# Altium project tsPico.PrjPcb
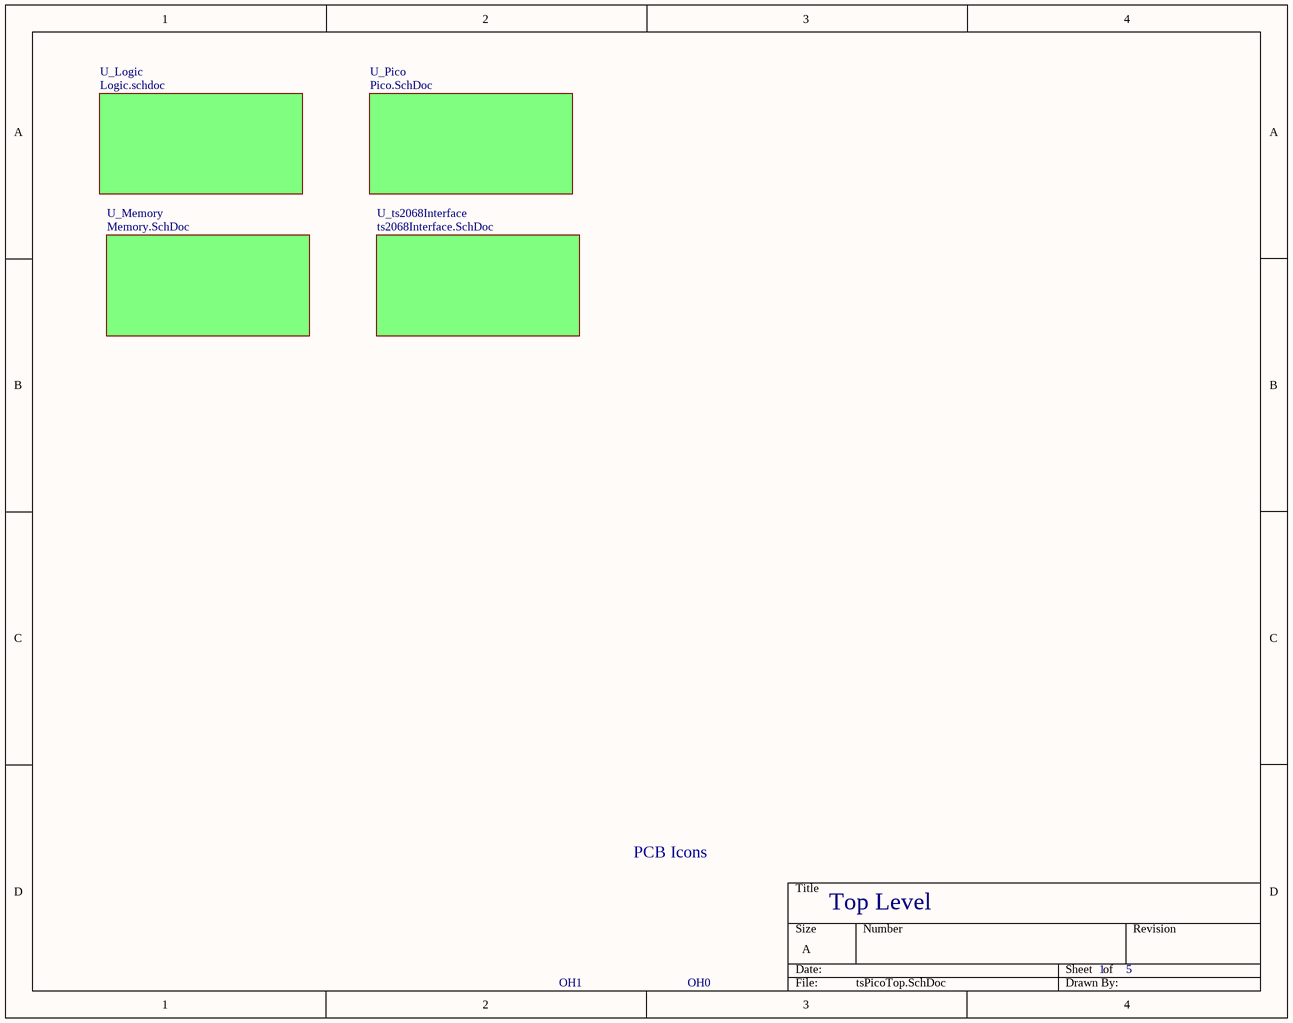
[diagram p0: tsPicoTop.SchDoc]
5 sheets, 52 parts. Net scope: global (net labels, ports and power ports of the same name join across sheets).
Sheets:
  tsPicoTop.SchDoc
    U_Logic = Logic.schdoc
    U_Memory = Memory.SchDoc
    U_Pico = Pico.SchDoc
    U_ts2068Interface = ts2068Interface.SchDoc

## Sheet tsPicoTop.SchDoc
size A; SheetNumber: 1; SheetTotal: 5

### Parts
OH0  OPENHW_PCB  [OpenHW]  (value not drawn)
OH1  OPENHW_SCH  (value not drawn)

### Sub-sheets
U_Logic = Logic.schdoc: no entries
U_Memory = Memory.SchDoc: no entries
U_Pico = Pico.SchDoc: no entries
U_ts2068Interface = ts2068Interface.SchDoc: no entries

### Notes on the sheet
- PCB Icons
- Top Level

## Sheet Logic.schdoc
size A; SheetNumber: 3; SheetTotal: 5
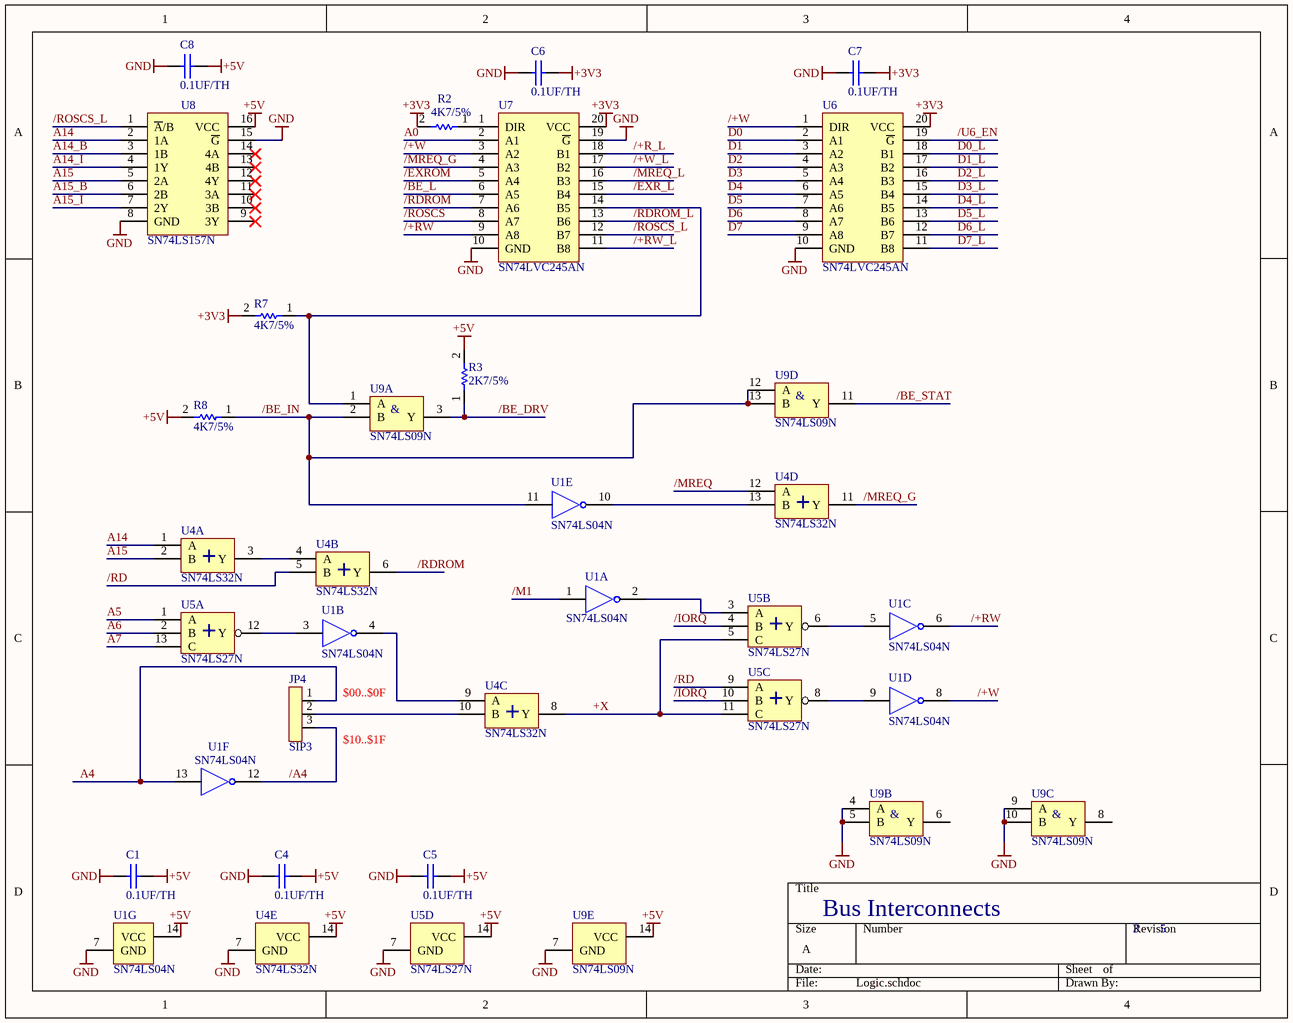
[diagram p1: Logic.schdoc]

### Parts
C1  0.1UF/TH  [CAPH5]
C4  0.1UF/TH  [CAPH5]
C5  0.1UF/TH  [CAPH5]
C6  0.1UF/TH  [CAPH5]
C7  0.1UF/TH  [CAPH5]
C8  0.1UF/TH  [CAPH5]
JP4  SIP3  [SIP3]
R2  4K7/5%  [CF18]
R3  2K7/5%  [CF18]
R7  4K7/5%  [CF18]
R8  4K7/5%  [CF18]
U1  SN74LS04N  [dip14]  (parts A,B,C,D,E,F,G of 7)
U4  SN74LS32N  [dip14]  (parts A,B,C,D,E of 5)
U5  SN74LS27N  [dip14]  (parts A,B,C,D of 4)
U6  SN74LVC245AN  [DIP20]
U7  SN74LVC245AN  [DIP20]
U8  SN74LS157N  [DIP16]
U9  SN74LS09N  [dip14]  (parts A,B,C,D,E of 5)

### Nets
+3V3: C6.2 C7.2 R2.2 R7.2 U6.20(VCC) U7.20(VCC)
+5V: C1.2 C4.2 C5.2 C8.2 R3.2 R8.2 U1.14(VCC) U4.14(VCC) U5.14(VCC) U8.16(VCC) U9.14(VCC)
GND: C1.1 C4.1 C5.1 C6.1 C7.1 C8.1 U1.7(GND) U4.7(GND) U5.7(GND) U6.10(GND) U7.10(GND) U7.19(~{G}) U8.8(GND) U8.15(~{G}) U9.4(A) U9.5(B) U9.7(GND) U9.9(A) U9.10(B)
+X: U4.8(Y) U5.5(C) U5.11(C)
/+R_L: U7.18(B1)
/+RW: U1.6 U7.9(A8)
/+RW_L: U7.11(B8)
/+W: U1.8 U6.1(DIR) U7.3(A2)
/+W_L: U7.17(B2)
/A4: JP4.3 U1.12
/BE_DRV: R3.1 U9.3(Y)
/BE_IN: R8.1 U1.11 U9.2(B) U9.12(A) U9.13(B)
/BE_L: U7.6(A5)
/BE_STAT: U9.11(Y)
/EXR_L: U7.15(B4)
/EXROM: U7.5(A4)
/IORQ: U5.4(B) U5.10(B)
/M1: U1.1
/MREQ: U4.12(A)
/MREQ_G: U4.11(Y) U7.4(A3)
/MREQ_L: U7.16(B3)
/RD: U4.5(B) U5.9(A)
/RDROM: U4.6(Y) U7.7(A6)
/RDROM_L: U7.13(B6)
/ROSCS: U7.8(A7)
/ROSCS_L: U7.12(B7) U8.1(~{A}/B)
/U6_EN: U6.19(~{G})
A0: U7.2(A1)
A4: JP4.1 U1.13
A5: U5.1(A)
A6: U5.2(B)
A7: U5.13(C)
A14: U4.1(A) U8.2(1A)
A14_B: U8.3(1B)
A14_I: U8.4(1Y)
A15: U4.2(B) U8.5(2A)
A15_B: U8.6(2B)
A15_I: U8.7(2Y)
D0: U6.2(A1)
D0_L: U6.18(B1)
D1: U6.3(A2)
D1_L: U6.17(B2)
D2: U6.4(A3)
D2_L: U6.16(B3)
D3: U6.5(A4)
D3_L: U6.15(B4)
D4: U6.6(A5)
D4_L: U6.14(B5)
D5: U6.7(A6)
D5_L: U6.13(B6)
D6: U6.8(A7)
D6_L: U6.12(B7)
D7: U6.9(A8)
D7_L: U6.11(B8)
NetJP4_2: JP4.2 U4.10(B)
NetR2_1: R2.1 U7.1(DIR)
NetR7_1: R7.1 U7.14(B5) U9.1(A)
NetU1_2: U1.2 U5.3(A)
NetU1_3: U1.3 U5.12(Y)
NetU1_4: U1.4 U4.9(A)
NetU1_5: U1.5 U5.6(Y)
NetU1_9: U1.9 U5.8(Y)
NetU1_10: U1.10 U4.13(B)
NetU4_3: U4.3(Y) U4.4(A)

Not connected (* = marked no-connect by the designer): U8 9(3Y)* 10(3B)* 11(3A)* 12(4Y)* 13(4B)* 14(4A)*; U9 6(Y) 8(Y)

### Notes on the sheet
- $00..$0F
- (near JP4) $10..$1F
- Bus Interconnects

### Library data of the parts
C1 C4-C8 = 0.1UF/TH: 0.1 µF ±10% 50V Ceramic Capacitor X7R Radial; MFG: Vishay; MFG PN: K104K10X7RF5UH5; DK PN: BC2665CT-ND
R2 R7 R8 = 4K7/5%: RES 4.7K OHM 5% 1/8W AXIAL; MFG PN: CF18JT4K70; DK PN: CF18JT4K70CT-ND; MFG: Stackpole
R3 = 2K7/5%: RES 2.7K OHM 5% 1/8W AXIAL; MFG PN: CF18JT2K70; DK PN: CF18JT2K70CT-ND; MFG: Stackpole
U1 = SN74LS04N: Inverter IC 6 Channel 14-PDIP; MFG: TI; DK PN: 296-1629-5-ND
U4 = SN74LS32N: IC GATE OR 4CH 2-INP 14DIP; MFG: TI; DK PN: 296-1658-5-ND
U5 = SN74LS27N: NOR Gate IC 3 Channel 14-PDIP; MFG: TI; DK PN: 296-14890-5-ND
U6 U7 = SN74LVC245AN: Transceiver, Non-Inverting 1 Element 8 Bit per Element 3-State Output 20-PDIP; MFG: TI; DK PN: 296-8503-5-ND
U8 = SN74LS157N: IC MULTIPLEXER 4 X 2:1 16DIP; MFG: TI; DK PN: 296-1645-5-ND
U9 = SN74LS09N: AND Gate IC 4 Channel Open Collector 14-PDIP; MFG: TI; DK PN: 296-3631-5-ND

## Sheet Memory.SchDoc
size A; SheetNumber: 4; SheetTotal: 5
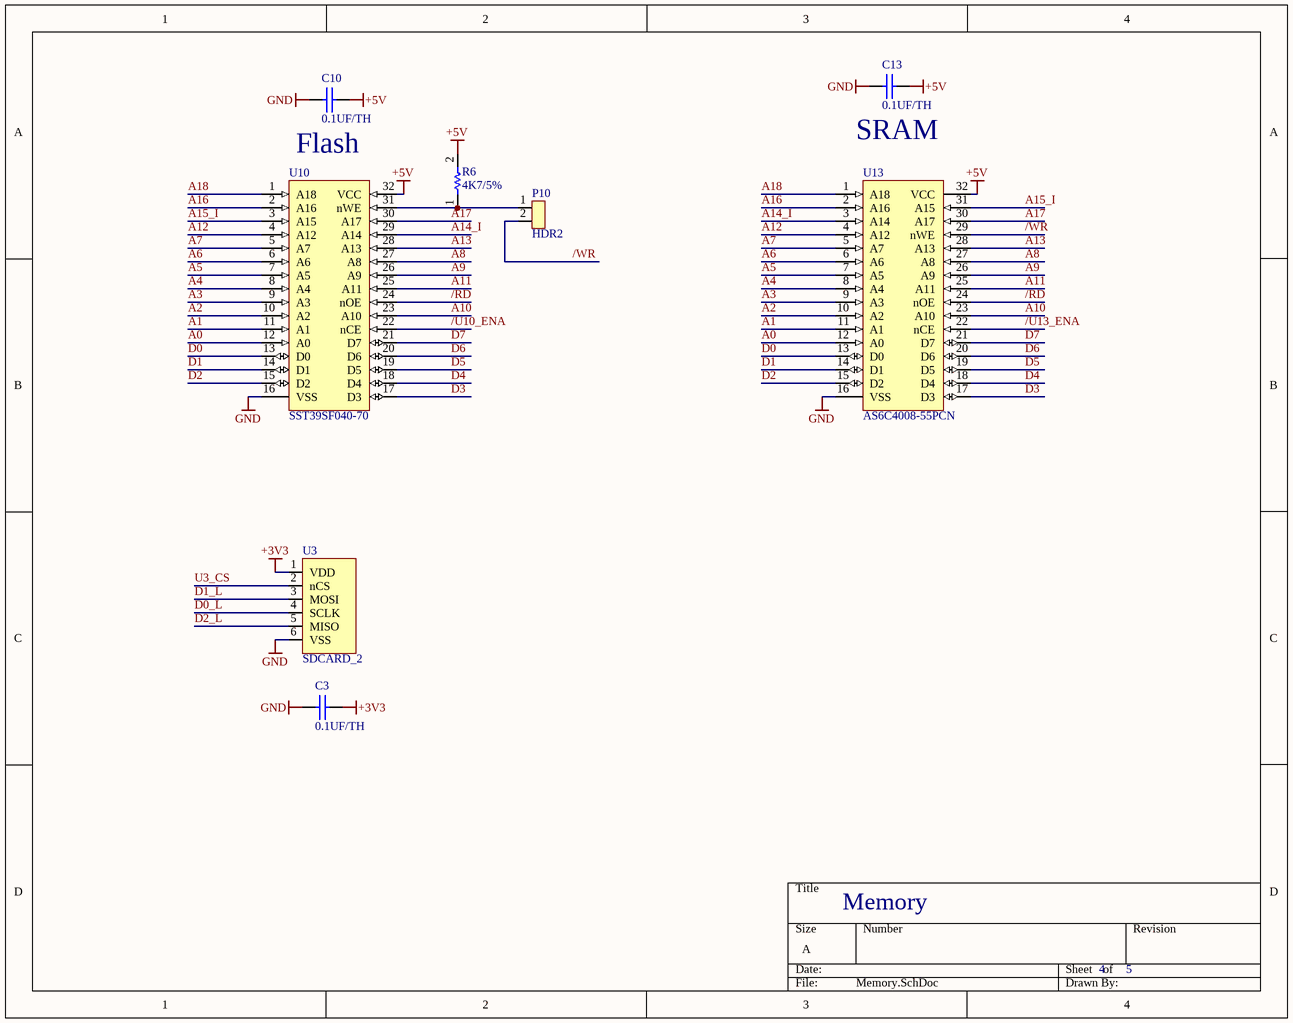
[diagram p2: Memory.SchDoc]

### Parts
C3  0.1UF/TH  [CAPH5]
C10  0.1UF/TH  [CAPH5]
C13  0.1UF/TH  [CAPH5]
P10  HDR2  [HDR2]
R6  4K7/5%  [CF18]
U3  SDCARD_2  [SDMODULE1_FLIPPED]
U10  SST39SF040-70  [DIP32]
U13  AS6C4008-55PCN  [DIP32]

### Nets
+3V3: C3.2 U3.1(VDD)
+5V: C10.2 C13.2 R6.2 U10.32(VCC) U13.32(VCC)
GND: C3.1 C10.1 C13.1 U3.6(VSS) U10.16(VSS) U13.16(VSS)
/RD: U10.24(nOE) U13.24(nOE)
/U10_ENA: U10.22(nCE)
/U13_ENA: U13.22(nCE)
/WR: P10.2 U13.29(nWE)
A0: U10.12(A0) U13.12(A0)
A1: U10.11(A1) U13.11(A1)
A2: U10.10(A2) U13.10(A2)
A3: U10.9(A3) U13.9(A3)
A4: U10.8(A4) U13.8(A4)
A5: U10.7(A5) U13.7(A5)
A6: U10.6(A6) U13.6(A6)
A7: U10.5(A7) U13.5(A7)
A8: U10.27(A8) U13.27(A8)
A9: U10.26(A9) U13.26(A9)
A10: U10.23(A10) U13.23(A10)
A11: U10.25(A11) U13.25(A11)
A12: U10.4(A12) U13.4(A12)
A13: U10.28(A13) U13.28(A13)
A14_I: U10.29(A14) U13.3(A14)
A15_I: U10.3(A15) U13.31(A15)
A16: U10.2(A16) U13.2(A16)
A17: U10.30(A17) U13.30(A17)
A18: U10.1(A18) U13.1(A18)
D0: U10.13(D0) U13.13(D0)
D0_L: U3.4(SCLK)
D1: U10.14(D1) U13.14(D1)
D1_L: U3.3(MOSI)
D2: U10.15(D2) U13.15(D2)
D2_L: U3.5(MISO)
D3: U10.17(D3) U13.17(D3)
D4: U10.18(D4) U13.18(D4)
D5: U10.19(D5) U13.19(D5)
D6: U10.20(D6) U13.20(D6)
D7: U10.21(D7) U13.21(D7)
U3_CS: U3.2(nCS)
NetP10_1: P10.1 R6.1 U10.31(nWE)

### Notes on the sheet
- Flash
- (near C13) SRAM
- Memory

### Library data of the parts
C3 C10 C13 = 0.1UF/TH: as C1 on sheet Logic
R6 = 4K7/5%: as R2 on sheet Logic
U3 = SDCARD_2: Micro SD card module; MFG: TE; MFG PN: 2041021-4; DK PN: A101492CT-ND
U10 = SST39SF040-70: FLASH Memory IC 4Mbit Parallel 70 ns 32-PDIP; MFG: Microchip; MFG PN: SST39SF040-70-4C-PHE; DK PN: SST39SF040-70-4C-PHE-ND
U13 = AS6C4008-55PCN: SRAM - Asynchronous Memory IC 4Mb (512K x 8) Parallel 55 ns 32-DIP; MFG: Alliance Memory, Inc.; DK PN: 1450-1027-ND

## Sheet Pico.SchDoc: Mass Storage
size A; SheetNumber: 4; SheetTotal: 7
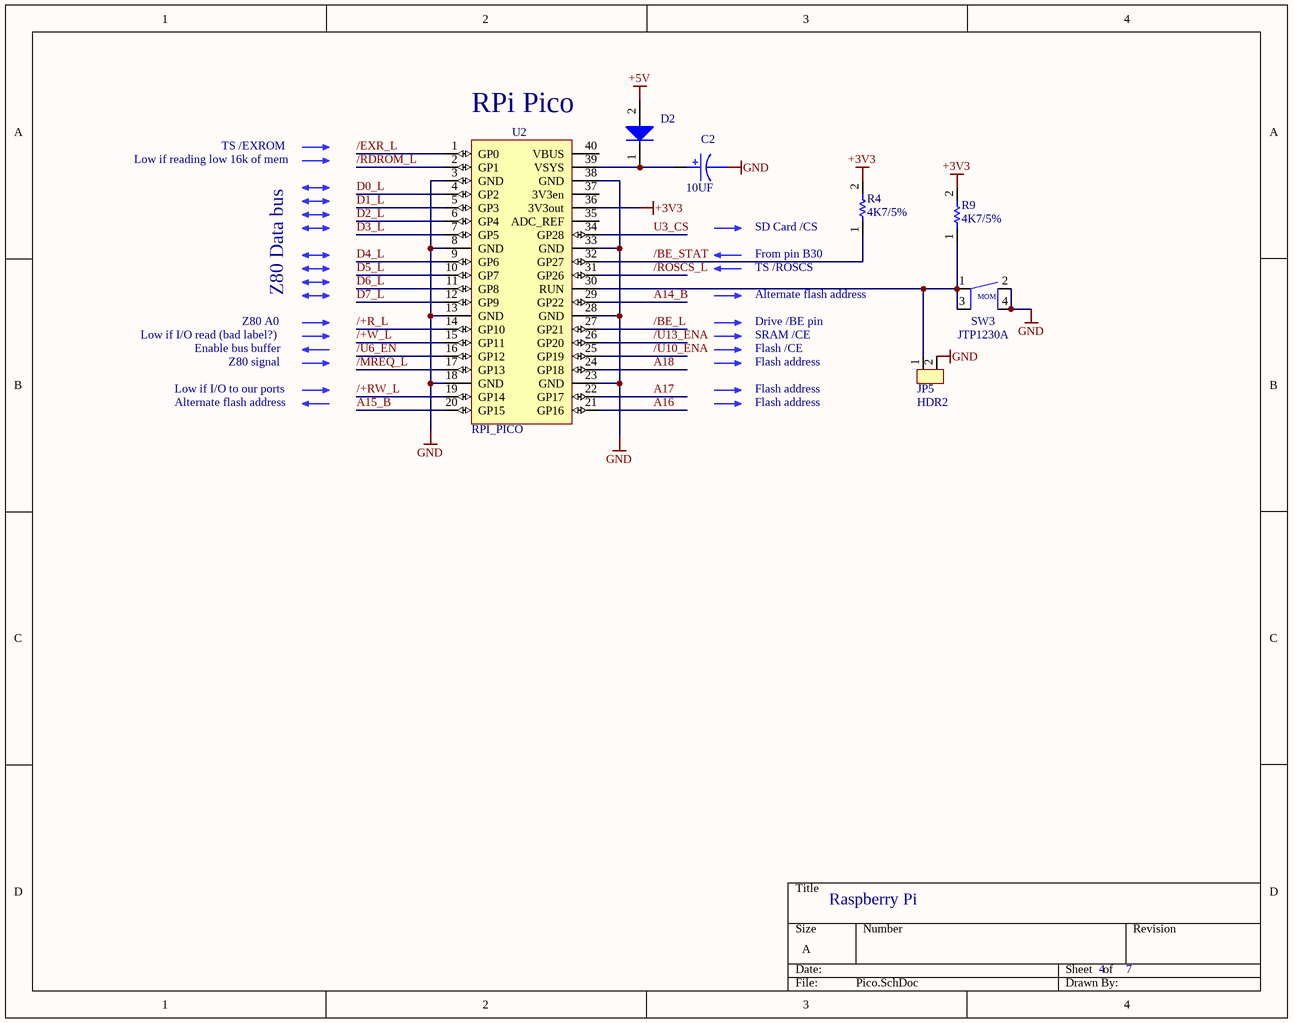
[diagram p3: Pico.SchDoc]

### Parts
C2  10UF  [CAP10EL]
D2  SB260_R2_00001  [DO-15]  (value not drawn)
JP5  HDR2  [HDR2]
R4  4K7/5%  [CF18]
R9  4K7/5%  [CF18]
SW3  JTP1230A  [TACSW_6.5x4.5]
U2  RPI_PICO  [RPIPICO]

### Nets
+3V3: R4.2 R9.2 U2.36(3V3out)
+5V: D2.2(A)
GND: C2.2 JP5.2 SW3.2 SW3.4 U2.3(GND) U2.8(GND) U2.13(GND) U2.18(GND) U2.23(GND) U2.28(GND) U2.33(GND) U2.38(GND)
/+R_L: U2.14(GP10)
/+RW_L: U2.19(GP14)
/+W_L: U2.15(GP11)
/BE_L: U2.27(GP21)
/BE_STAT: R4.1 U2.32(GP27)
/EXR_L: U2.1(GP0)
/MREQ_L: U2.17(GP13)
/RDROM_L: U2.2(GP1)
/ROSCS_L: U2.31(GP26)
/U6_EN: U2.16(GP12)
/U10_ENA: U2.25(GP19)
/U13_ENA: U2.26(GP20)
A14_B: U2.29(GP22)
A15_B: U2.20(GP15)
A16: U2.21(GP16)
A17: U2.22(GP17)
A18: U2.24(GP18)
D0_L: U2.4(GP2)
D1_L: U2.5(GP3)
D2_L: U2.6(GP4)
D3_L: U2.7(GP5)
D4_L: U2.9(GP6)
D5_L: U2.10(GP7)
D6_L: U2.11(GP8)
D7_L: U2.12(GP9)
U3_CS: U2.34(GP28)
NetC2_1: C2.1 D2.1 U2.39(VSYS)
NetJP5_1: JP5.1 R9.1 SW3.1 SW3.3 U2.30(RUN)

Not connected (* = marked no-connect by the designer): U2 35(ADC_REF) 37(3V3en) 40(VBUS)

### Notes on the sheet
- Low if reading low 16k of mem
- TS /EXROM
- RPi Pico
- (near R4) SD Card /CS
- Z80 Data bus
- TS /ROSCS
- (near R4) From pin B30
- Alternate flash address
- Low if I/O read (bad label?)
- Enable bus buffer
- Z80 signal
- Z80 A0
- Drive /BE pin
- Flash /CE
- SRAM /CE
- Flash address
- Low if I/O to our ports
- Raspberry Pi

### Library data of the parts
C2 = 10UF: CAP ALUM 10UF 20% 16V RADIAL; MFG: Panasonic; MFG PN: ECE-A1CKA100; DK PN: P807-ND
D2 = SB260_R2_00001: DIODE SCHOTTKY 60V 2A DO15; DK PN: 3757-SB260_R2_00001CT-ND; MFG: Panjit
R4 R9 = 4K7/5%: as R2 on sheet Logic
SW3 = JTP1230A: Tactile Switch SPST-NO Top Actuated Through Hole; MFG: Apem; DK PN: 679-2429-ND
U2 = RPI_PICO: RASPBERRY PI PICO RP2040 BOARD; MFG PN: SC0915; DK PN: 2648-SC0915CT-ND

## Sheet ts2068Interface.SchDoc
size A; SheetNumber: 2; SheetTotal: 5
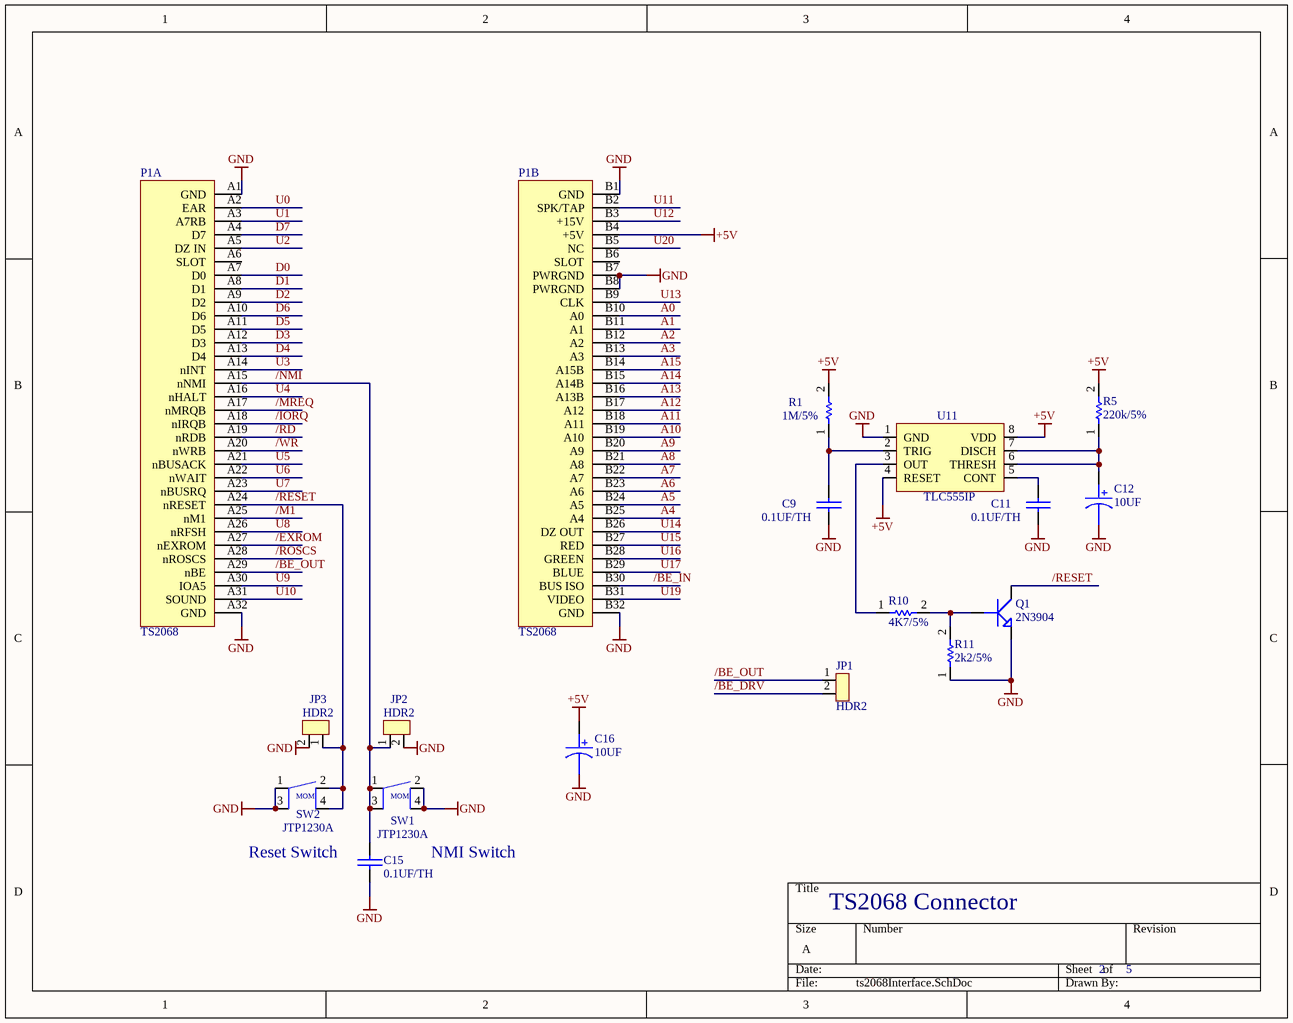
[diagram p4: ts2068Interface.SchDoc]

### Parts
C9  0.1UF/TH  [CAPH5]
C11  0.1UF/TH  [CAPH5]
C12  10UF  [CAP10EL]
C15  0.1UF/TH  [CAPH5]
C16  10UF  [CAP10EL]
JP1  HDR2  [HDR2]
JP2  HDR2  [HDR2]
JP3  HDR2  [HDR2]
P1  TS2068  [TS2068A]  (parts A,B of 2)
Q1  2N3904  [TO92]
R1  1M/5%  [CF18]
R5  220k/5%  [CF18]
R10  4K7/5%  [CF18]
R11  2k2/5%  [CF18]
SW1  JTP1230A  [TACSW_6.5x4.5]
SW2  JTP1230A  [TACSW_6.5x4.5]
U11  TLC555IP  [DIP8]

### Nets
+5V: C16.1 P1.B4(+5V) R1.2 R5.2 U11.4(RESET) U11.8(VDD)
GND: C9.1 C11.1 C12.2 C15.1 C16.2 JP2.2 JP3.2 P1.A1(GND) P1.A32(GND) P1.B1(GND) P1.B7(PWRGND) P1.B8(PWRGND) P1.B32(GND) Q1.1(EMITTER) R11.1 SW1.2 SW1.4 SW2.1 SW2.3 U11.1(GND)
/BE_DRV: JP1.2
/BE_IN: P1.B30(BUS_ISO)
/BE_OUT: JP1.1 P1.A29(nBE)
/EXROM: P1.A27(nEXROM)
/IORQ: P1.A18(nIRQB)
/M1: P1.A25(nM1)
/MREQ: P1.A17(nMRQB)
/NMI: C15.2 JP2.1 P1.A15(nNMI) SW1.1 SW1.3
/RD: P1.A19(nRDB)
/RESET: JP3.1 P1.A24(nRESET) Q1.3(COLLECTOR) SW2.2 SW2.4
/ROSCS: P1.A28(nROSCS)
/WR: P1.A20(nWRB)
A0: P1.B10(A0)
A1: P1.B11(A1)
A2: P1.B12(A2)
A3: P1.B13(A3)
A4: P1.B25(A4)
A5: P1.B24(A5)
A6: P1.B23(A6)
A7: P1.B22(A7)
A8: P1.B21(A8)
A9: P1.B20(A9)
A10: P1.B19(A10)
A11: P1.B18(A11)
A12: P1.B17(A12)
A13: P1.B16(A13B)
A14: P1.B15(A14B)
A15: P1.B14(A15B)
D0: P1.A7(D0)
D1: P1.A8(D1)
D2: P1.A9(D2)
D3: P1.A12(D3)
D4: P1.A13(D4)
D5: P1.A11(D5)
D6: P1.A10(D6)
D7: P1.A4(D7)
U0: P1.A2(EAR)
U1: P1.A3(A7RB)
U2: P1.A5(DZ_IN)
U3: P1.A14(nINT)
U4: P1.A16(nHALT)
U5: P1.A21(nBUSACK)
U6: P1.A22(nWAIT)
U7: P1.A23(nBUSRQ)
U8: P1.A26(nRFSH)
U9: P1.A30(IOA5)
U10: P1.A31(SOUND)
U11: P1.B2(SPK/TAP)
U12: P1.B3(+15V)
U13: P1.B9(CLK)
U14: P1.B26(DZ_OUT)
U15: P1.B27(RED)
U16: P1.B28(GREEN)
U17: P1.B29(BLUE)
U19: P1.B31(VIDEO)
U20: P1.B5(NC)
NetC9_2: C9.2 R1.1 U11.2(TRIG)
NetC11_2: C11.2 U11.5(CONT)
NetC12_1: C12.1 R5.1 U11.6(THRESH) U11.7(DISCH)
NetQ1_2: Q1.2(BASE) R10.2 R11.2
NetR10_1: R10.1 U11.3(OUT)

Not connected (* = marked no-connect by the designer): P1 A6(SLOT) B6(SLOT)

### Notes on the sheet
- (near C15) Reset Switch
- NMI Switch
- TS2068 Connector

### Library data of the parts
C9 C11 C15 = 0.1UF/TH: as C1 on sheet Logic
C12 C16 = 10UF: as C2 on sheet Pico
Q1 = 2N3904: TRANS NPN 40V 0.2A TO92; MFG: NTE; DK PN: 2368-2N3904-ND
R1 = 1M/5%: 1 MOhms ±5% 0.125W, 1/8W Through Hole Resistor Axial Flame Retardant Coating, Safety Carbon Film; MFG PN: CF18JT1M00; DK PN: CF18JT1M00CT-ND; MFG: Stackpole
R5 = 220k/5%: RES 220K OHM 5% 1/8W AXIAL; MFG PN: CF18JT220K; DK PN: CF18JT220KCT-ND; MFG: Stackpole
R10 = 4K7/5%: as R2 on sheet Logic
R11 = 2k2/5%: 2.2 kOhms ±5% 0.125W, 1/8W Through Hole Resistor Axial Flame Retardant Coating, Safety Carbon Film; MFG PN: CF18JT2K20; DK PN: CF18JT2K20CT-ND; MFG: Stackpole
SW1 SW2 = JTP1230A: as SW3 on sheet Pico
U11 = TLC555IP: 555 Type, Timer/Oscillator (Single) IC 2.1MHz 8-PDIP; MFG: TI; DK PN: 296-1858-5-ND

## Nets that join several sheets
+3V3: Logic (6 pins), Memory (C3.2 U3.1), Pico (R4.2 R9.2 U2.36)
+5V: Logic (11 pins), Memory (5 pins), Pico (D2.2), ts2068Interface (6 pins)
GND: Logic (19 pins), Memory (6 pins), Pico (12 pins), ts2068Interface (20 pins)
/+R_L: Logic (U7.18), Pico (U2.14)
/+RW_L: Logic (U7.11), Pico (U2.19)
/+W_L: Logic (U7.17), Pico (U2.15)
/BE_DRV: Logic (R3.1 U9.3), ts2068Interface (JP1.2)
/BE_IN: Logic (5 pins), ts2068Interface (P1.B30)
/BE_L: Logic (U7.6), Pico (U2.27)
/BE_STAT: Logic (U9.11), Pico (R4.1 U2.32)
/EXR_L: Logic (U7.15), Pico (U2.1)
/EXROM: Logic (U7.5), ts2068Interface (P1.A27)
/IORQ: Logic (U5.4 U5.10), ts2068Interface (P1.A18)
/M1: Logic (U1.1), ts2068Interface (P1.A25)
/MREQ: Logic (U4.12), ts2068Interface (P1.A17)
/MREQ_L: Logic (U7.16), Pico (U2.17)
/RD: Logic (U4.5 U5.9), Memory (U10.24 U13.24), ts2068Interface (P1.A19)
/RDROM_L: Logic (U7.13), Pico (U2.2)
/ROSCS: Logic (U7.8), ts2068Interface (P1.A28)
/ROSCS_L: Logic (U7.12 U8.1), Pico (U2.31)
/U6_EN: Logic (U6.19), Pico (U2.16)
/U10_ENA: Memory (U10.22), Pico (U2.25)
/U13_ENA: Memory (U13.22), Pico (U2.26)
/WR: Memory (P10.2 U13.29), ts2068Interface (P1.A20)
A0: Logic (U7.2), Memory (U10.12 U13.12), ts2068Interface (P1.B10)
A1: Memory (U10.11 U13.11), ts2068Interface (P1.B11)
A2: Memory (U10.10 U13.10), ts2068Interface (P1.B12)
A3: Memory (U10.9 U13.9), ts2068Interface (P1.B13)
A4: Logic (JP4.1 U1.13), Memory (U10.8 U13.8), ts2068Interface (P1.B25)
A5: Logic (U5.1), Memory (U10.7 U13.7), ts2068Interface (P1.B24)
A6: Logic (U5.2), Memory (U10.6 U13.6), ts2068Interface (P1.B23)
A7: Logic (U5.13), Memory (U10.5 U13.5), ts2068Interface (P1.B22)
A8: Memory (U10.27 U13.27), ts2068Interface (P1.B21)
A9: Memory (U10.26 U13.26), ts2068Interface (P1.B20)
A10: Memory (U10.23 U13.23), ts2068Interface (P1.B19)
A11: Memory (U10.25 U13.25), ts2068Interface (P1.B18)
A12: Memory (U10.4 U13.4), ts2068Interface (P1.B17)
A13: Memory (U10.28 U13.28), ts2068Interface (P1.B16)
A14: Logic (U4.1 U8.2), ts2068Interface (P1.B15)
A14_B: Logic (U8.3), Pico (U2.29)
A14_I: Logic (U8.4), Memory (U10.29 U13.3)
A15: Logic (U4.2 U8.5), ts2068Interface (P1.B14)
A15_B: Logic (U8.6), Pico (U2.20)
A15_I: Logic (U8.7), Memory (U10.3 U13.31)
A16: Memory (U10.2 U13.2), Pico (U2.21)
A17: Memory (U10.30 U13.30), Pico (U2.22)
A18: Memory (U10.1 U13.1), Pico (U2.24)
D0: Logic (U6.2), Memory (U10.13 U13.13), ts2068Interface (P1.A7)
D0_L: Logic (U6.18), Memory (U3.4), Pico (U2.4)
D1: Logic (U6.3), Memory (U10.14 U13.14), ts2068Interface (P1.A8)
D1_L: Logic (U6.17), Memory (U3.3), Pico (U2.5)
D2: Logic (U6.4), Memory (U10.15 U13.15), ts2068Interface (P1.A9)
D2_L: Logic (U6.16), Memory (U3.5), Pico (U2.6)
D3: Logic (U6.5), Memory (U10.17 U13.17), ts2068Interface (P1.A12)
D3_L: Logic (U6.15), Pico (U2.7)
D4: Logic (U6.6), Memory (U10.18 U13.18), ts2068Interface (P1.A13)
D4_L: Logic (U6.14), Pico (U2.9)
D5: Logic (U6.7), Memory (U10.19 U13.19), ts2068Interface (P1.A11)
D5_L: Logic (U6.13), Pico (U2.10)
D6: Logic (U6.8), Memory (U10.20 U13.20), ts2068Interface (P1.A10)
D6_L: Logic (U6.12), Pico (U2.11)
D7: Logic (U6.9), Memory (U10.21 U13.21), ts2068Interface (P1.A4)
D7_L: Logic (U6.11), Pico (U2.12)
U3_CS: Memory (U3.2), Pico (U2.34)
